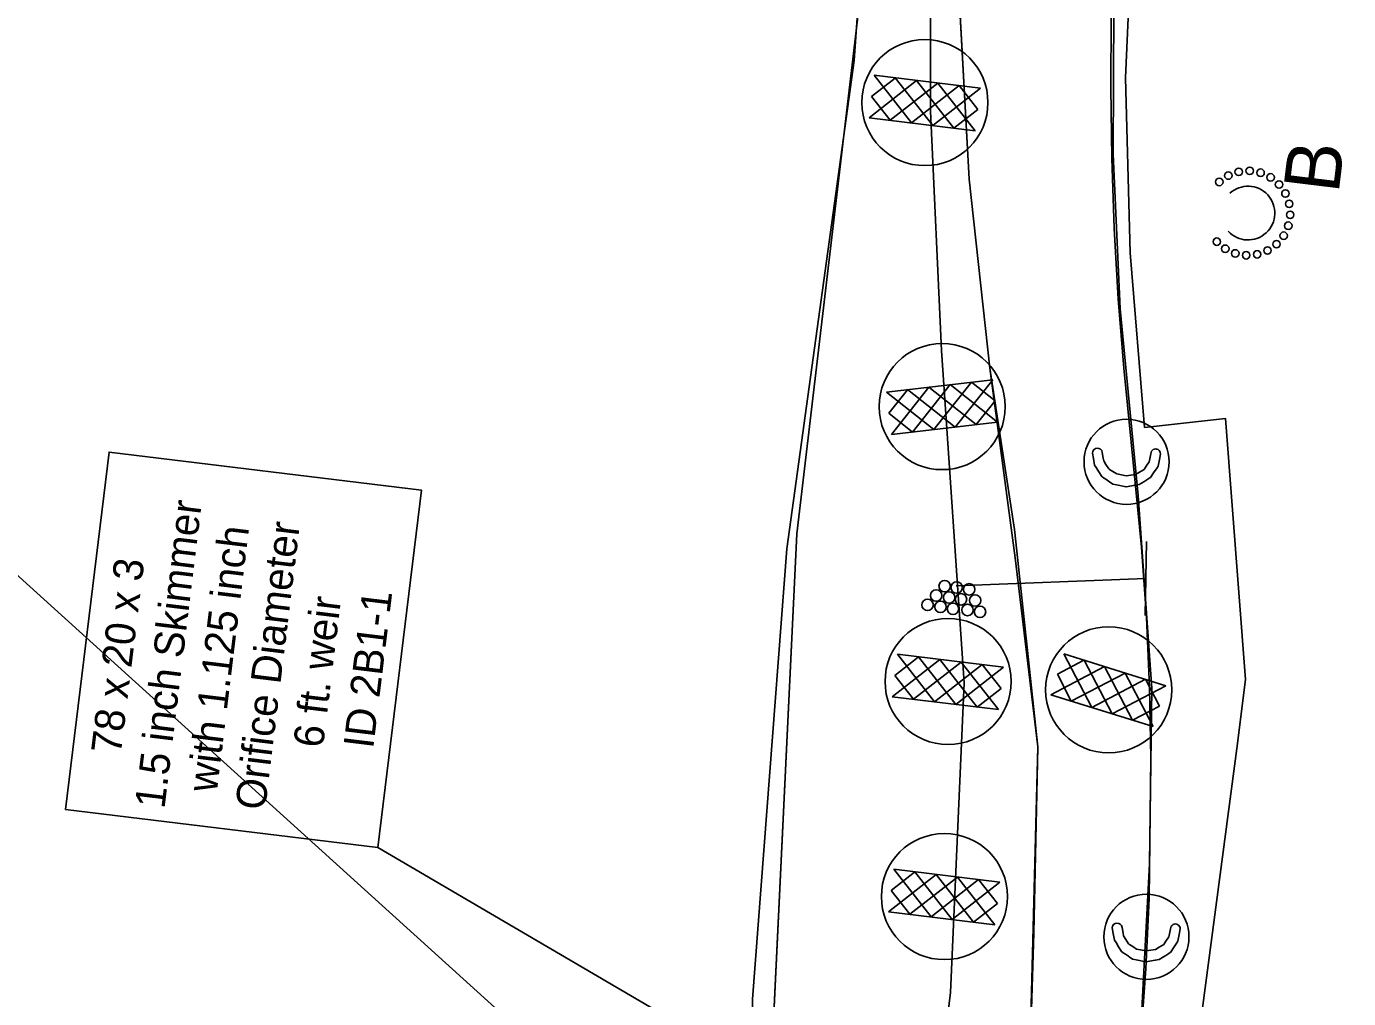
# Model space of a CAD drawing. Extents: x 400935 to 481562, y 415700 to 505362.
# Drawn here: x 480870.3 to 481227.5, y 489531.4 to 489794.1 of the extents above; entities that cross this region are included whole.
import ezdxf

# ---------------------------------------------------------------- set-up
doc = ezdxf.new("R2010")
doc.units = 0
for name, color, linetype in [('Coir Fiber Wattle with PAM Final CELL', 7, 'Continuous'), ('Drain Terminator Final CELL', 7, 'Continuous'), ('Earth Berm Final', 7, 'Continuous'), ('Label B Final CELL', 7, 'Continuous'), ('Left Flow Clean Water Diversion Both', 7, 'Continuous'), ('Matting on Slope Note Final CELL', 7, 'Continuous'), ('Prop Grid Mask', 7, 'Continuous'), ('Rock Pipe Inlet Sediment Trap Type B Final CELL', 7, 'Continuous'), ('Rock Silt Check Type A with Matting and PAM CG CELL', 7, 'Continuous'), ('Rock Silt Check Type A with Matting and PAM Final CELL', 7, 'Continuous'), ('Scratch_Level_4', 7, 'Continuous'), ('Skimmer Basin Note Both CELL', 7, 'Continuous'), ('Slope Drain Final', 7, 'Continuous'), ('Slope Drain Inlet Final CELL', 7, 'Continuous'), ('Temporary Silt Ditch Both', 7, 'Continuous'), ('Total Drainage Area Border Both Drainage', 7, 'Continuous')]:
    doc.layers.add(name, color=color, linetype=linetype)

msp = doc.modelspace()

# ---------------------------------------------------------------- linework, layer by layer
at = {"layer": 'Coir Fiber Wattle with PAM Final CELL'}
for p, q in [((481160.95, 489678.99), (481161.2, 489677.45)), ((481161.2, 489677.45), (481161.33, 489676.67)), ((481173.67, 489676.81), (481174.05, 489678.63)), ((481161.33, 489676.67), (481161.92, 489675.74)), ((481161.92, 489675.74), (481162.7, 489674.52)), ((481162.9, 489674.39), (481162.7, 489674.52)), ((481162.9, 489674.39), (481163.83, 489673.79)), ((481164.84, 489673.15), (481163.83, 489673.79)), ((481170.97, 489673.65), (481172.21, 489674.39)), ((481172.21, 489674.39), (481172.78, 489675.25)), ((481172.78, 489675.25), (481173.61, 489676.48)), ((481173.67, 489676.81), (481173.61, 489676.48)), ((481164.84, 489673.15), (481167.42, 489672.65)), ((481167.43, 489672.65), (481167.42, 489672.65)), ((481167.43, 489672.65), (481169.94, 489673.03)), ((481169.94, 489673.03), (481170.97, 489673.65)), ((481166.3, 489550.64), (481166.54, 489549.11)), ((481166.54, 489549.11), (481166.67, 489548.33)), ((481179.02, 489548.46), (481179.39, 489550.28)), ((481166.67, 489548.33), (481167.27, 489547.4)), ((481167.27, 489547.4), (481168.05, 489546.17)), ((481168.25, 489546.05), (481168.05, 489546.17)), ((481168.25, 489546.05), (481169.18, 489545.44)), ((481170.18, 489544.8), (481169.18, 489545.44)), ((481175.29, 489544.69), (481176.32, 489545.3)), ((481176.32, 489545.3), (481177.56, 489546.05)), ((481177.56, 489546.05), (481178.13, 489546.9)), ((481178.13, 489546.9), (481178.95, 489548.13)), ((481179.02, 489548.46), (481178.95, 489548.13)), ((481170.18, 489544.8), (481172.76, 489544.3)), ((481172.78, 489544.3), (481172.76, 489544.3)), ((481172.78, 489544.3), (481175.29, 489544.69))]:
    msp.add_line(p, q, dxfattribs=at)
for points in [[(481176.64, 489678.59), (481176.35, 489677.06), (481176.01, 489675.27), (481175.55, 489674.58), (481174.99, 489673.73), (481174, 489672.24), (481173.97, 489672.21), (481173.6, 489671.98), (481173.53, 489671.94), (481172.72, 489671.43), (481172.16, 489671.07), (481170.92, 489670.29), (481169.9, 489670.11), (481167.38, 489669.67), (481167.37, 489669.67), (481164.79, 489670.21), (481163.78, 489670.42), (481162.85, 489671.06), (481162.65, 489671.19), (481161.86, 489671.74), (481161.26, 489672.15), (481161.12, 489672.25), (481160.81, 489672.45), (481160.81, 489672.46), (481160.01, 489673.74), (481159.3, 489674.88), (481158.87, 489675.57), (481158.56, 489677.3), (481158.29, 489678.82)], [(481181.99, 489550.24), (481181.7, 489548.71), (481181.36, 489546.93), (481180.9, 489546.23), (481180.34, 489545.38), (481179.35, 489543.89), (481179.32, 489543.87), (481178.94, 489543.63), (481178.88, 489543.59), (481178.07, 489543.08), (481177.51, 489542.72), (481176.27, 489541.94), (481175.24, 489541.76), (481172.73, 489541.33), (481172.72, 489541.33), (481170.13, 489541.86), (481169.13, 489542.07), (481168.19, 489542.71), (481168, 489542.85), (481167.2, 489543.39), (481166.6, 489543.8), (481166.46, 489543.9), (481166.16, 489544.11), (481166.15, 489544.11), (481165.35, 489545.4), (481164.65, 489546.53), (481164.22, 489547.22), (481163.91, 489548.95), (481163.64, 489550.48)]]:
    msp.add_lwpolyline(points, dxfattribs=at)
for centre in [(481167.5, 489676.45), (481172.85, 489548.1)]:
    msp.add_circle(centre, 11.5, dxfattribs=at)
for centre, radius, start in [((481159.63, 489678.8), 1.33, 7.986), ((481175.35, 489678.61), 1.3, 359.0986), ((481164.97, 489550.46), 1.33, 7.986), ((481180.69, 489550.26), 1.3, 359.0986)]:
    msp.add_arc(centre, radius, start, 179.0986, dxfattribs=at)
at = {"layer": 'Drain Terminator Final CELL'}
for centre in [(481116.06, 489640.31), (481118.37, 489642.84), (481121.61, 489642.49), (481124.97, 489641.98), (481113.75, 489637.77), (481117.25, 489637.24), (481119.55, 489639.78), (481120.61, 489636.73), (481122.78, 489639.29), (481124.54, 489636.41), (481126.58, 489638.99), (481127.9, 489635.91)]:
    msp.add_circle(centre, 1.55, dxfattribs=at)
at = {"layer": 'Earth Berm Final'}
msp.add_lwpolyline([(481212.19, 490248.38), (481198.72, 490124.18), (481186.82, 490014.53), (481173.7, 489911.46), (481166.37, 489853.86), (481164.05, 489799.4), (481163.89, 489759.7), (481165.78, 489717.82), (481170.64, 489667.3), (481174.33, 489615.2), (481173.71, 489567.81), (481171.39, 489523.3), (481166.26, 489479.02), (481158.82, 489435.07), (481154.27, 489408.23), (481147.12, 489381.96), (481137.73, 489356.4)], dxfattribs=at)
at = {"layer": 'Left Flow Clean Water Diversion Both'}
msp.add_lwpolyline([(481108.92, 489998.35), (481093.89, 489784.84), (481075.74, 489652.97), (481066.42, 489531.25), (481066.69, 489412.89), (481093.37, 489383.38)], dxfattribs=at)
at = {"layer": 'Matting on Slope Note Final CELL'}
for p, q in [((481122.2, 489803.5), (481124.96, 489752.79)), ((481124.96, 489752.79), (481130.59, 489701.73)), ((481130.59, 489701.73), (481137.19, 489658.12)), ((481137.19, 489658.12), (481143.55, 489599.4))]:
    msp.add_line(p, q, dxfattribs=at)
for points in [[(481140.98, 489501.82), (481142.43, 489549.17), (481143.55, 489599.4), (481137.19, 489658.12), (481130.59, 489701.73), (481124.96, 489752.79), (481122.2, 489803.5)], [(481138.69, 489352.66), (481143.94, 489367.81), (481149.66, 489389.45), (481158.02, 489426.52), (481164.65, 489463.93), (481169.54, 489501.61), (481172.67, 489539.48), (481173.59, 489558.46), (481174.09, 489596.45), (481173.68, 489615.45), (481172.87, 489634.37), (481171.54, 489653.38), (481168.78, 489681.75), (481166.72, 489701.78), (481165.26, 489720.49), (481164.14, 489739.46), (481163.48, 489758.45), (481163.24, 489777.45), (481163.38, 489796.44)], [(481163.38, 489796.44), (481163.24, 489777.45), (481163.48, 489758.45), (481164.14, 489739.46), (481165.26, 489720.49), (481166.72, 489701.78), (481168.78, 489681.75), (481171.54, 489653.38), (481172.87, 489634.37), (481173.68, 489615.45), (481174.09, 489596.45), (481173.59, 489558.46), (481172.67, 489539.48), (481171.32, 489520.53)], [(481143.55, 489599.4), (481140.98, 489501.82), (481135.14, 489454.78), (481124.52, 489408.57), (481122.97, 489357.38)]]:
    msp.add_lwpolyline(points, dxfattribs=at)
at = {"layer": 'Prop Grid Mask'}
msp.add_lwpolyline([(480880.89, 489582.53), (480892.66, 489679.07), (480977.01, 489668.78), (480965.23, 489572.24)], close=True, dxfattribs=at)
at = {"layer": 'Rock Pipe Inlet Sediment Trap Type B Final CELL'}
for centre in [(481200.76, 489755.07), (481192.55, 489752.06), (481194.99, 489753.78), (481197.79, 489754.8), (481203.7, 489754.55), (481206.41, 489753.3), (481208.69, 489751.38), (481210.41, 489748.94), (481211.43, 489746.14), (481211.7, 489743.17), (481209.93, 489737.53), (481211.18, 489740.23), (481191.87, 489735.92), (481194.16, 489734.01), (481205.57, 489733.53), (481208.01, 489735.24), (481196.86, 489732.75), (481199.8, 489732.24), (481202.77, 489732.5)]:
    msp.add_circle(centre, 1.01, dxfattribs=at)
msp.add_arc((481200.28, 489743.65), 7.26, 222.5912, 132.5824, dxfattribs=at)
at = {"layer": 'Rock Silt Check Type A with Matting and PAM CG CELL'}
for p, q in [((481150.52, 489624.55), (481178.11, 489615.93)), ((481158.1, 489610.08), (481150.52, 489624.55)), ((481161.55, 489621.1), (481147.08, 489613.52)), ((481155.95, 489622.8), (481148.8, 489619.06)), ((481163.64, 489608.35), (481156.01, 489622.83)), ((481169.13, 489606.64), (481161.55, 489621.1)), ((481152.57, 489611.81), (481148.8, 489619.06)), ((481167.08, 489619.37), (481152.57, 489611.81)), ((481172.58, 489617.67), (481158.1, 489610.08)), ((481174.67, 489604.91), (481167.08, 489619.37)), ((481176.41, 489610.44), (481172.58, 489617.67)), ((481147.08, 489613.52), (481174.67, 489604.91)), ((481178.11, 489615.93), (481163.64, 489608.35)), ((481176.41, 489610.44), (481169.13, 489606.64))]:
    msp.add_line(p, q, dxfattribs=at)
msp.add_circle((481162.67, 489614.84), 17.04, dxfattribs=at)
at = {"layer": 'Rock Silt Check Type A with Matting and PAM Final CELL'}
for p, q in [((481099.32, 489780.88), (481128.01, 489777.37)), ((481109.39, 489768.01), (481099.32, 489780.88)), ((481110.79, 489779.48), (481097.92, 489769.41)), ((481104.97, 489780.14), (481098.61, 489775.17)), ((481116.54, 489778.77), (481103.63, 489768.71)), ((481115.14, 489767.31), (481105.03, 489780.18)), ((481122.25, 489778.09), (481109.39, 489768.01)), ((481120.85, 489766.61), (481110.79, 489779.48)), ((481128.01, 489777.37), (481115.14, 489767.31)), ((481126.61, 489765.91), (481116.54, 489778.77)), ((481127.32, 489771.67), (481122.25, 489778.09)), ((481103.63, 489768.71), (481098.61, 489775.17)), ((481127.32, 489771.67), (481120.85, 489766.61)), ((481097.92, 489769.41), (481126.61, 489765.91)), ((481102.63, 489695.29), (481131.34, 489698.63)), ((481115.44, 489685.15), (481102.63, 489695.29)), ((481108.3, 489695.9), (481103.28, 489689.58)), ((481114.1, 489696.63), (481103.97, 489683.82)), ((481121.2, 489685.82), (481108.34, 489695.95)), ((481119.86, 489697.3), (481109.68, 489684.48)), ((481126.91, 489686.49), (481114.1, 489696.63)), ((481125.57, 489697.98), (481115.44, 489685.15)), ((481132.67, 489687.16), (481119.86, 489697.3)), ((481131.34, 489698.63), (481121.2, 489685.82)), ((481132.01, 489692.92), (481125.57, 489697.98)), ((481132.01, 489692.92), (481126.91, 489686.49)), ((481109.68, 489684.48), (481103.28, 489689.58)), ((481103.97, 489683.82), (481132.67, 489687.16)), ((481111.24, 489623.69), (481104.88, 489618.72)), ((481105.59, 489624.43), (481134.27, 489620.93)), ((481115.65, 489611.57), (481105.59, 489624.43)), ((481121.41, 489610.86), (481111.29, 489623.73)), ((481117.05, 489623.03), (481104.19, 489612.97)), ((481122.81, 489622.33), (481109.9, 489612.27)), ((481128.52, 489621.64), (481115.65, 489611.57)), ((481127.12, 489610.17), (481117.05, 489623.03)), ((481134.27, 489620.93), (481121.41, 489610.86)), ((481132.88, 489609.47), (481122.81, 489622.33)), ((481133.59, 489615.22), (481128.52, 489621.64)), ((481109.9, 489612.27), (481104.88, 489618.72)), ((481104.19, 489612.97), (481132.88, 489609.47)), ((481133.59, 489615.22), (481127.12, 489610.17)), ((481116.06, 489564.94), (481103.2, 489554.87)), ((481110.25, 489565.59), (481103.89, 489560.63)), ((481104.6, 489566.34), (481133.29, 489562.83)), ((481114.67, 489553.47), (481104.6, 489566.34)), ((481121.82, 489564.23), (481108.91, 489554.17)), ((481120.42, 489552.77), (481110.31, 489565.64)), ((481127.53, 489563.55), (481114.67, 489553.47)), ((481126.13, 489552.07), (481116.06, 489564.94)), ((481131.89, 489551.37), (481121.82, 489564.23)), ((481132.6, 489557.12), (481127.53, 489563.55)), ((481108.91, 489554.17), (481103.89, 489560.63)), ((481133.29, 489562.83), (481120.42, 489552.77)), ((481132.6, 489557.12), (481126.13, 489552.07)), ((481103.2, 489554.87), (481131.89, 489551.37))]:
    msp.add_line(p, q, dxfattribs=at)
for centre in [(481113.02, 489773.51), (481117.68, 489691.36), (481119.29, 489617.07), (481118.3, 489558.97)]:
    msp.add_circle(centre, 17.04, dxfattribs=at)
at = {"layer": 'Scratch_Level_4'}
for points in [[(480877.24, 490463.31), (480982.54, 490200.49), (481151.83, 490261.85), (481107.68, 489905.23), (481078.42, 489657), (481066.69, 489412.89), (481003.5, 489522.94), (480707.43, 489791.02), (480585.75, 489869.24), (480505.56, 489977.09), (480447.46, 490122.86), (480351.3, 490280.03)], [(481122.2, 489803.5), (481124.96, 489752.79), (481130.59, 489701.73), (481137.39, 489650.53), (481143.55, 489599.4), (481142.43, 489549.17), (481140.98, 489501.82), (481135.14, 489454.78), (481124.52, 489408.57), (481168.23, 489410.36), (481181.2, 489477.11), (481197.26, 489598.97), (481199.62, 489617.63), (481194.22, 489688.17), (481172.36, 489685.75), (481168.48, 489732.89), (481167.24, 489780.17), (481170.35, 489851.13)]]:
    msp.add_lwpolyline(points, dxfattribs=at)
at = {"layer": 'Skimmer Basin Note Both CELL'}
msp.add_line((480965.23, 489572.24), (481102.58, 489491.79), dxfattribs=at)
msp.add_lwpolyline([(480880.89, 489582.53), (480892.66, 489679.07), (480977.01, 489668.78), (480965.23, 489572.24)], close=True, dxfattribs=at)
at = {"layer": 'Slope Drain Final'}
msp.add_line((481172.68, 489644.93), (481121.46, 489642.97), dxfattribs=at)
at = {"layer": 'Slope Drain Inlet Final CELL'}
msp.add_line((481172.53, 489634.93), (481172.84, 489654.93), dxfattribs=at)
at = {"layer": 'Temporary Silt Ditch Both'}
msp.add_lwpolyline([(481114.37, 489487.15), (481119.96, 489533.01), (481123.6, 489616.7), (481117.5, 489706.49), (481114.49, 489771.18), (481114.56, 489852.86), (481111.18, 489905.59)], dxfattribs=at)
at = {"layer": 'Total Drainage Area Border Both Drainage'}
msp.add_lwpolyline([(481069.47, 489470.84), (481123.91, 489406.63), (481168.23, 489410.36), (481181.2, 489477.11), (481197.26, 489598.97), (481199.62, 489617.63), (481194.22, 489688.17), (481172.36, 489685.75), (481168.48, 489732.89), (481167.24, 489780.17), (481170.35, 489851.13), (481175.52, 489897.91), (481181.18, 489944.23), (481192.1, 489942.89), (481230.44, 490256.86), (481151.83, 490261.85), (481107.68, 489905.23), (481078.42, 489657)], close=True, dxfattribs=at)

# ---------------------------------------------------------------- texts
at = {"layer": 'Label B Final CELL'}
msp.add_text('B', height=15, rotation=83.0423, dxfattribs=at).set_placement((481224.75, 489748.71))
at = {"layer": 'Skimmer Basin Note Both CELL'}
for s, p in [('1.5 inch Skimmer', (480907.59, 489582.51)), ('Orifice Diameter', (480934.74, 489582.1)), ('with 1.125 inch', (480921.73, 489586.94)), ('78 x 20 x 3', (480895.79, 489597.25)), ('6 ft. weir', (480950.4, 489598.94)), ('ID 2B1-1', (480963.97, 489598.75))]:
    msp.add_text(s, height=8.1, rotation=83.0452, dxfattribs=at).set_placement(p)

doc.saveas('drawing.dxf')
